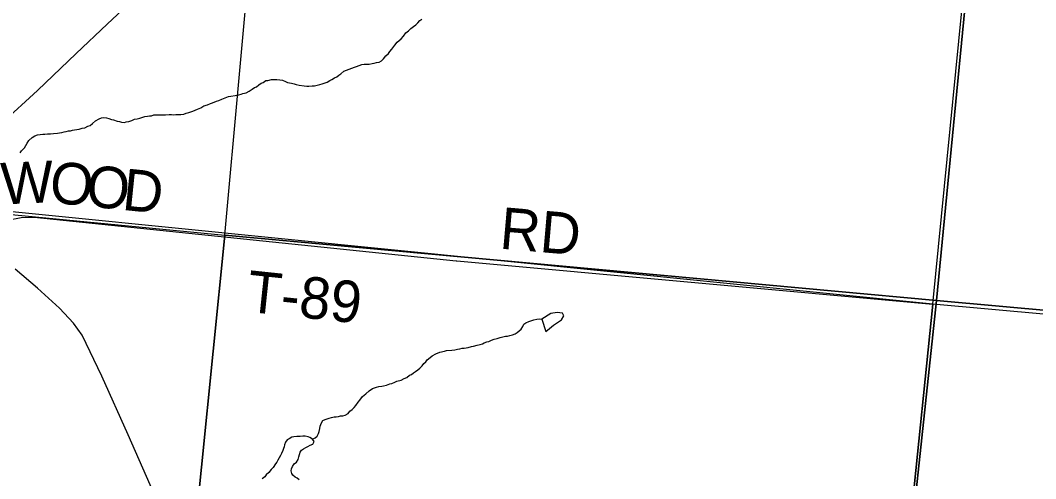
# Model space of a CAD drawing. Extents: x 0 to 34, y -4 to 22.
# Drawn here: x 7.021 to 7.996, y 18.994 to 19.435 of the extents above; entities that cross this region are included whole.
import ezdxf

# ---------------------------------------------------------------- set-up
doc = ezdxf.new("R2010")
doc.units = 0
for name, color, linetype in [('GM_X_County_Road', 7, 'Continuous'), ('GM_X_Interstate_Route', 7, 'Continuous'), ('GM_X_Minor_Lake', 7, 'Continuous'), ('GM_X_Minor_River', 7, 'Continuous'), ('GM_X_Section', 7, 'Continuous'), ('GM_X_Township', 7, 'Continuous'), ('GM_X_Township_Road', 7, 'Continuous'), ('GM_X_Township_Road_Text', 7, 'Continuous')]:
    doc.layers.add(name, color=color, linetype=linetype)

msp = doc.modelspace()

# ---------------------------------------------------------------- linework, layer by layer
at = {"layer": 'GM_X_County_Road'}
msp.add_lwpolyline([(7.33601, 18.25915), (7.33871, 18.2913), (7.34504, 18.3792), (7.35391, 18.50329), (7.35447, 18.52578), (7.35407, 18.53188), (7.35225, 18.53711), (7.34607, 18.55453), (7.30553, 18.63705), (7.27602, 18.69741), (7.25608, 18.73799), (7.19979, 18.86517), (7.1245, 19.03628), (7.09929, 19.09268), (7.08034, 19.13223), (7.07191, 19.14375), (7.05849, 19.15812), (7.03734, 19.17736), (7.01597, 19.19565)], dxfattribs=at)
at = {"layer": 'GM_X_Interstate_Route'}
msp.add_lwpolyline([(7.00321, 19.33597), (7.03741, 19.36727), (7.07441, 19.40305), (7.10426, 19.43124), (7.13823, 19.46335)], dxfattribs=at)
at = {"layer": 'GM_X_Minor_Lake'}
for points in [[(7.52187, 19.14746), (7.5256, 19.13559), (7.52916, 19.13845), (7.53298, 19.14157), (7.53789, 19.14493), (7.54089, 19.147), (7.54312, 19.15069), (7.54157, 19.15314), (7.5365, 19.15379), (7.53058, 19.15287)], [(7.53058, 19.15287), (7.52187, 19.14746)], [(7.28866, 18.99284), (7.28684, 18.9945), (7.285, 18.99563), (7.28265, 18.9973), (7.28164, 18.9992), (7.28118, 19.00162), (7.28124, 19.00349), (7.28239, 19.00586), (7.28381, 19.00822), (7.28601, 19.01002), (7.2877, 19.01237), (7.28832, 19.01503), (7.28921, 19.0174), (7.28981, 19.01952), (7.29094, 19.02136), (7.29287, 19.0229), (7.29506, 19.02417), (7.29696, 19.02518), (7.29942, 19.02644), (7.30186, 19.02743), (7.30301, 19.0298), (7.30148, 19.03198), (7.29912, 19.03366), (7.29726, 19.03425), (7.2946, 19.03487), (7.2922, 19.03494), (7.28978, 19.03475), (7.28656, 19.03458), (7.28361, 19.0344), (7.28171, 19.03393), (7.27925, 19.0324), (7.27708, 19.0314), (7.27566, 19.02904), (7.27451, 19.02667), (7.27418, 19.02481), (7.27358, 19.02296), (7.27299, 19.02111), (7.27182, 19.01821), (7.27069, 19.01637), (7.26955, 19.01427), (7.26839, 19.0119), (7.26726, 19.01007), (7.26613, 19.00823), (7.26361, 19.00484), (7.26193, 19.00275), (7.2597, 19.00015), (7.25695, 18.99783), (7.25581, 18.99599), (7.25307, 18.99394)]]:
    msp.add_lwpolyline(points, dxfattribs=at)
at = {"layer": 'GM_X_Minor_River'}
for points in [[(7.2115, 19.35773), (7.21449, 19.35898), (7.21774, 19.36021), (7.22073, 19.36146), (7.22316, 19.36192), (7.2272, 19.36259), (7.23071, 19.36329), (7.23286, 19.36375), (7.23476, 19.3645), (7.23773, 19.36521), (7.24073, 19.36672), (7.24348, 19.36877), (7.24567, 19.3703), (7.24784, 19.37104), (7.25004, 19.37284), (7.25224, 19.37438), (7.25414, 19.37512), (7.25661, 19.37691), (7.25849, 19.37712), (7.26226, 19.37781), (7.26521, 19.37798), (7.26736, 19.37792), (7.27029, 19.37756), (7.27269, 19.37722), (7.2756, 19.37606), (7.27745, 19.3752), (7.28144, 19.37428), (7.28383, 19.37367), (7.28595, 19.37307), (7.28861, 19.37245), (7.29369, 19.37203), (7.29609, 19.37169), (7.29796, 19.37163), (7.30118, 19.3718), (7.30333, 19.372), (7.30602, 19.37245), (7.30846, 19.37317), (7.31089, 19.3739), (7.3136, 19.37462), (7.31577, 19.37535), (7.31823, 19.37688), (7.32013, 19.37789), (7.3226, 19.37942), (7.32478, 19.38068), (7.32671, 19.38223), (7.32863, 19.3835), (7.33166, 19.38608), (7.33436, 19.3868), (7.33925, 19.38879), (7.34196, 19.38977), (7.34386, 19.39052), (7.3463, 19.39151), (7.34902, 19.39249), (7.35117, 19.39269), (7.35304, 19.39264), (7.35599, 19.39281), (7.35895, 19.39325), (7.36085, 19.39373), (7.363, 19.3942), (7.36543, 19.39466), (7.36788, 19.39592), (7.36982, 19.39773), (7.37206, 19.4006), (7.37454, 19.40292), (7.37595, 19.40502), (7.3779, 19.4071), (7.38071, 19.41102), (7.38294, 19.41389), (7.3868, 19.41697), (7.38902, 19.41957), (7.39127, 19.42271), (7.39375, 19.42477), (7.39597, 19.42711), (7.39844, 19.4289), (7.40091, 19.43069), (7.40285, 19.4325), (7.40479, 19.43458), (7.40672, 19.43613)], [(7.0207, 19.30752), (7.02209, 19.30935), (7.02487, 19.3122), (7.02602, 19.31457), (7.02743, 19.31666), (7.02912, 19.31928), (7.03216, 19.32213), (7.0349, 19.32391), (7.03734, 19.32464), (7.04003, 19.32509), (7.04245, 19.32528), (7.04433, 19.32549), (7.04701, 19.32568), (7.04997, 19.32585), (7.05265, 19.32604), (7.05642, 19.32645), (7.05857, 19.32666), (7.06073, 19.32712), (7.06288, 19.32759), (7.06477, 19.3278), (7.0672, 19.32853), (7.06908, 19.32874), (7.07097, 19.32921), (7.07286, 19.32942), (7.07528, 19.32988), (7.07744, 19.33035), (7.08041, 19.33106), (7.08284, 19.33152), (7.08584, 19.33303), (7.088, 19.33376), (7.09021, 19.33556), (7.09297, 19.33815), (7.09652, 19.34018), (7.0987, 19.34118), (7.10085, 19.34138), (7.10378, 19.34102), (7.10591, 19.34042), (7.10829, 19.33955), (7.11042, 19.33922), (7.11387, 19.33804), (7.11626, 19.33743), (7.11811, 19.33684), (7.12079, 19.33676), (7.12268, 19.33723), (7.12511, 19.33769), (7.12809, 19.33867), (7.13053, 19.33966), (7.13296, 19.34012), (7.13566, 19.34084), (7.14053, 19.34229), (7.14295, 19.34275), (7.14484, 19.34296), (7.14699, 19.34316), (7.14915, 19.3439), (7.15211, 19.34407), (7.15478, 19.34399), (7.15773, 19.3439), (7.16041, 19.34408), (7.1639, 19.34424), (7.16604, 19.34418), (7.16845, 19.3441), (7.17033, 19.34431), (7.17301, 19.34423), (7.17515, 19.34416), (7.17785, 19.34461), (7.18002, 19.34562), (7.18273, 19.34633), (7.18652, 19.34755), (7.18869, 19.34855), (7.19113, 19.34928), (7.19439, 19.35078), (7.19713, 19.35257), (7.20065, 19.35353), (7.20363, 19.35477), (7.20553, 19.35551), (7.20933, 19.357), (7.2115, 19.35773)], [(7.30148, 19.03198), (7.3042, 19.03324), (7.30613, 19.03505), (7.30729, 19.03768), (7.30789, 19.03953), (7.30852, 19.04245), (7.30886, 19.04458), (7.31003, 19.04775), (7.31145, 19.05011), (7.31363, 19.05111), (7.31742, 19.05233), (7.31985, 19.05279), (7.32228, 19.05351), (7.32443, 19.05371), (7.32658, 19.05392), (7.32847, 19.05439), (7.33062, 19.05459), (7.33306, 19.05532), (7.33579, 19.05684), (7.33746, 19.05892), (7.33966, 19.06046), (7.3416, 19.06254), (7.34327, 19.06435), (7.34552, 19.06776), (7.34692, 19.06958), (7.34971, 19.07297), (7.35275, 19.07581), (7.35606, 19.07865), (7.35908, 19.0807), (7.36315, 19.08217), (7.3653, 19.08264), (7.368, 19.08309), (7.36988, 19.0833), (7.37258, 19.08402), (7.37584, 19.08525), (7.37773, 19.08573), (7.38072, 19.08697), (7.38263, 19.08798), (7.38668, 19.08893), (7.38967, 19.09044), (7.39212, 19.09143), (7.39486, 19.09348), (7.39676, 19.09422), (7.3987, 19.09603), (7.40061, 19.09704), (7.40281, 19.09885), (7.40474, 19.10039), (7.40696, 19.10273), (7.40837, 19.10482), (7.41029, 19.10636), (7.4117, 19.10846), (7.41472, 19.1105), (7.41665, 19.11231), (7.41993, 19.11408), (7.424, 19.11582), (7.42832, 19.11676), (7.43021, 19.11723), (7.43531, 19.11761), (7.43827, 19.11805), (7.44097, 19.1185), (7.44313, 19.11897), (7.44529, 19.11944), (7.44717, 19.11965), (7.44905, 19.11986), (7.45121, 19.12033), (7.45418, 19.12104), (7.45634, 19.1215), (7.45958, 19.12247), (7.46255, 19.12318), (7.46472, 19.12392), (7.46662, 19.12466), (7.46907, 19.12565), (7.47096, 19.12613), (7.47341, 19.12739), (7.47611, 19.1281), (7.47908, 19.12882), (7.48179, 19.1298), (7.4845, 19.13052), (7.48692, 19.13098), (7.48881, 19.13119), (7.49123, 19.13165), (7.49367, 19.13237), (7.49611, 19.13336), (7.4983, 19.13463), (7.50022, 19.13618), (7.50189, 19.138), (7.50358, 19.14035), (7.50473, 19.14272), (7.50665, 19.14399), (7.50937, 19.14524), (7.51235, 19.14622), (7.51424, 19.1467), (7.51694, 19.14741), (7.51937, 19.14787), (7.52187, 19.14746)]]:
    msp.add_lwpolyline(points, dxfattribs=at)
at = {"layer": 'GM_X_Section'}
for points in [[(6.55968, 20.0213), (6.48626, 19.29903), (7.21731, 19.22831), (7.28612, 19.985), (6.9086, 20.0213)], [(7.28612, 19.985), (7.97405, 19.91801), (7.90105, 19.1654), (7.21731, 19.22831)], [(7.97405, 19.91801), (8.66411, 19.85205), (8.59171, 19.1029), (7.90105, 19.1654)], [(6.48626, 19.29903), (7.21731, 19.22831), (7.15014, 18.55903), (6.41744, 18.64125)], [(7.90105, 19.1654), (7.82864, 18.48717), (7.15014, 18.55903), (7.21731, 19.22831)], [(7.90105, 19.1654), (8.59171, 19.1029), (8.52385, 18.41099), (7.82864, 18.48717)]]:
    msp.add_lwpolyline(points, close=True, dxfattribs=at)
at = {"layer": 'GM_X_Township'}
for points in [[(7.70395, 17.41086), (7.82296, 18.48336), (7.8558, 18.75422), (7.89749, 19.16191), (6.95864, 19.25607)], [(8.9, 14.99227), (8.9, 19.07101), (8.74356, 19.08501), (8.61662, 19.09679), (7.89749, 19.16191), (7.8558, 18.75422), (7.82296, 18.48336), (7.70395, 17.41086)]]:
    msp.add_lwpolyline(points, dxfattribs=at)
at = {"layer": 'GM_X_Township_Road'}
for points in [[(7.89749, 19.16191), (7.89749, 19.16191), (7.93631, 19.55446), (7.9429, 19.59781)], [(6.97819, 19.23224), (6.98912, 19.23711), (7.00848, 19.24281), (7.02167, 19.2453), (7.03426, 19.24566), (7.43972, 19.20353), (7.44012, 19.2035)], [(7.44012, 19.2035), (7.89749, 19.16191)], [(7.84963, 18.75008), (7.85133, 18.75122), (7.8558, 18.75422), (7.89749, 19.16191)]]:
    msp.add_lwpolyline(points, dxfattribs=at)

# ---------------------------------------------------------------- texts
at = {"layer": 'GM_X_Township_Road_Text'}
for s, rotation, p in [('W', 2.62643, (7.00295, 19.25772)), ('O', 354.22018, (7.0477, 19.25989)), ('O', 354.10273, (7.0827, 19.25635)), ('D', 354.1047, (7.11771, 19.25273)), ('RD', 355.07189, (7.4805, 19.21542)), ('T-89', 353.97305, (7.23719, 19.15476))]:
    msp.add_text(s, height=0.04, rotation=rotation, dxfattribs=at).set_placement(p)

doc.saveas('drawing.dxf')
